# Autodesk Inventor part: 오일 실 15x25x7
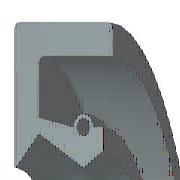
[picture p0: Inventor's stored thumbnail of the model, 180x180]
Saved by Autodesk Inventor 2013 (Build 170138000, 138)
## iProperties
Created: 2012-02
Part Number: 오일 실 15x25x7
Material: 고무
Description: 오일-실
Document SubType Name: Modeling
Standard: KS B 2804
Designer: mduedu
Standards Organization: KS
Language: ko-KR
Size Designation: D - 15 25 7
Categories: <MemberInstance><Categories><Category DisplayName="샤프트 부품" InternalName="7f7aeb1f-a693-4053-b835-cee3144e0d98" Mnemonic="SHFT"><Category DisplayName="실링" Intern
Density: 0.93 g/cm^3
IsCustomPart: 1
Author: mduedu
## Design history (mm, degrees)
revolve "본체" stored, may be unused: angle "d17" = 90 deg
revolve "스프링1" stored, may be unused: angle "d18" = 90 deg
body "Solid1"
sketch "스케치1"
  geometry: L1 (0, 12.5)-(7, 12.5); L2 (7, 10.75)-(1.75, 10.75); L3 (1.75, 9.25)-(4.9, 7.5); L4 (4.9, 7.5)-(0, 7.5); L5 (0, 0)-(9.586, 0) reference; L6 (4.9, 7.5)-(6.3, 8.375); L7 (0, 18)-(0, -3) reference; L8 (-1.941, 0)-(11.507, 0) reference; L9 (4.2, 9.6)-(1.75, 10.09); L10 (1.75, 10.09)-(1.75, 10.75); L11 (0, 12.5)-(0, 7.588); L12 (4.9, 7.5)-(0, 7.5); L13 (1.75, 9.25)-(0.152, 7.528); L14 (7, 12.5)-(7, 10.75); L15 (5.6, 9.6)-(6.3, 9.6); L16 (6.3, 9.6)-(6.3, 8.375); C1 r 0.455 at (4.9, 9.6); A1 r 0.7 centre (4.9, 9.6) between (5.6, 9.6) and (4.2, 9.6); A2 r 0.088 centre (0.088, 7.588) between (0, 7.588) and (0.152, 7.528); 1 further point
  constraints: 28 end point, 5 horizontal alignment, 5 point on line, 4 point on circle, 4 vertical alignment, 3 centre point, 3 tangent, 2 collinear, 2 horizontal, 2 perpendicular, 1 coincident, 1 parallel
  dimensions: "d0" = 25 diameter of L1 L5 (= SD2); "d1" = 1.75 distance of L1.end L2.start (= SD); "d2" = 0.91 diameter of C1 (= SPDI); "d3" = 1.4 diameter of A1 (= SPDA); "d4" = 15 diameter of L3.end L5 (= NND); "d5" = 18.5 diameter of L3.start L5 (= TKDM); "d7" = 20.18 diameter of L9.end L5 (= TKDM + 0.24 x SWDT); "d8" = 1.75 distance between parallel lines of L11 L10 (= SD); "d9" = 4.9 distance from line of L11 C1.centre (= SPDST); "d10" = 19.2 diameter of C1.centre L5 (= HLDM); "d11" = 0.0875 radius of A2 (= 0.25 x LAB); "d12" = 6.3 distance between parallel lines of L11 L16 (= SDI); "d13" = 16.75 diameter of L6.end L5 (= ABDM); "d14" = 7 distance from line of L11 L1.end (= SWDT)
fillet "모깎기1" dims "d6" = 0.3 (= RR)
other parameters: "SD2" = 25 [user parameter; used in 1 equation term], "SWDT" = 7 [user parameter; used in 2 equation terms], "RR" = 0.3 [user parameter; used in 1 equation term], "SD" = 1.75 [user parameter; used in 2 equation terms], "NND" = 15 [user parameter; used in 1 equation term], "SPDA" = 1.4 [user parameter; used in 1 equation term], "SPDI" = 0.91 [user parameter; used in 1 equation term], "TKDM" = 18.5 [user parameter; used in 2 equation terms], "HLDM" = 19.2 [user parameter; used in 1 equation term], "ABDM" = 16.75 [user parameter; used in 1 equation term], "SDI" = 6.3 [user parameter; used in 1 equation term], "SPDST" = 4.9 [user parameter; used in 1 equation term], "LAB" = 0.35 [user parameter; used in 1 equation term], "d15" = 0, "d16" = 0, "d19" = 0
